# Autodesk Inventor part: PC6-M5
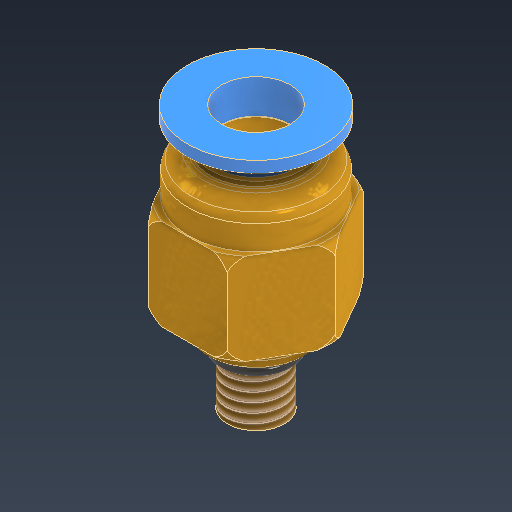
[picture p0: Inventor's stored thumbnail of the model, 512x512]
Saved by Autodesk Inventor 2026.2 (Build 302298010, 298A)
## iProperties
Created: 2026-04
Part Number: PC6-M5
Material: 황동, 연질 노란색, 용접
Document SubType Name: Modeling
Designer: khw
Density: 8.5 g/cm^3
Appearance: 용접 - 황동
Author: khw
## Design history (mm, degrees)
sketch "스케치1"
  geometry: C1 r 2.5 at (0, 0); 1 further point
  constraints: 1 centre point, 1 coincident
  dimensions: "d0" = 5 diameter of C1
extrude "돌출1" new body sketch "스케치1" distance "d1" = 5; taper "d2" = 0 deg
sketch "스케치2"
  geometry: L1 (0, 0)-(8, 0); L2 (8, 0)-(8, -4.5); L3 (5, -2.5)-(5, 2.5) reference; L4 (5, -2.5)-(6.155, -4.5); L5 (6.155, -4.5)-(8, -4.5); 2 further points
  constraints: 8 end point, 2 perpendicular, 1 horizontal, 1 midpoint
  dimensions: "d3" = 3 distance between parallel lines of L2 L3; "d5" = 150 deg angle of L3 L4; "d19" = 9 diameter of point (7.077, -4.5) L1
revolve "회전1" sketch "스케치2" stored, may be unused: angle "d6" = 90 deg
sketch "스케치3"
  geometry: L1 (-6.928, 0)-(-3.464, 6); L2 (-3.464, 6)-(3.464, 6); L3 (3.464, 6)-(6.928, 0); L4 (6.928, 0)-(3.464, -6); L5 (3.464, -6)-(-3.464, -6); L6 (-3.464, -6)-(-6.928, 0); L7 (0, 0)-(-6.928, 0); 1 further point
  constraints: 14 end point, 1 coincident, 1 horizontal, 13 other
  dimensions: "d7" = 12 distance between parallel lines of L3 L6
extrude "돌출2" join sketch "스케치3" distance "d8" = 8; taper "d9" = 0 deg
node "작업 평면1"
sketch "스케치7"
  geometry: L1 (-3.464, 8)-(3.464, 8) reference; L2 (3.464, 8)-(3.464, 16) reference; L3 (-3.464, 16)-(3.464, 16) reference; L4 (-3.464, 8)-(-3.464, 16) reference; L5 (-3.464, 16)-(3.464, 16) reference; L6 (0, 16)-(0, 20); L7 (0, 20)-(4, 20); L8 (4, 20)-(4, 19.6); L9 (4, 19.6)-(4.4, 19.6); L10 (3.464, 16)-(6.928, 16) reference; L11 (5.928, 18.5)-(5.928, 16); L12 (3, 20)-(3, 23); L13 (3, 23)-(0, 23); L14 (3.6, 20)-(3.6, 22); L15 (3.6, 22)-(6, 22); L16 (6, 22)-(6, 23); L17 (6, 23)-(3, 23); L18 (0, 20)-(0, 23); A1 r 3 centre (3.5, 16.738) between (5.928, 18.5) and (4.4, 19.6); 3 further points
  constraints: 24 end point, 8 perpendicular, 4 vertical, 3 point on line, 2 midpoint, 2 point on circle, 1 centre point
  dimensions: "d27" = 0.4 distance of L7.end L8.end; "d28" = 4 distance of L6.end L7.end; "d29" = 0.4 distance of L8.end L9.end; "d30" = 3 radius of A1; "d31" = 4 distance from line of L3 point (2, 20); "d32" = 1 distance from line of L10.end L11; "d33" = 2.5 distance of L11.end L11.start; "d34" = 6 diameter of L12 L6; "d35" = 3 distance between parallel lines of L7 L13; "d36" = 1 distance between parallel lines of L17 L15; "d37" = 0.4 distance from line of L7.end L14; "d38" = 12 diameter of L16 L6
revolve "회전4" sketch "스케치7" stored, may be unused: angle "d39" = 90 deg
sketch "스케치8"
  geometry: C1 r 2.936 at (0, 0); 1 further point
  constraints: 1 centre point, 1 coincident
extrude "돌출3" cut sketch "스케치8" stored distance "d40" = 8; taper "d41" = 0 deg
sketch "스케치9"
  geometry: C1 r 1.5 at (0, 0); 1 further point
  constraints: 1 centre point, 1 coincident
  dimensions: "d42" = 3 diameter of C1
extrude "돌출4" cut sketch "스케치9" distance "d43" = 10; taper "d44" = 0 deg
feature "스레드1" dims "d45" = 5, "d46" = 0
sketch "스케치10"
  geometry: L1 (5, -2.5)-(5, 2.5) reference; L2 (0, 0)-(5, 0); C1 r 0.375 at (4.8, -2.8)
  constraints: 2 end point, 1 centre point, 1 midpoint
  dimensions: "d47" = 0.75 diameter of C1; "d48" = 0.2 distance from line of L1 C1.centre; "d49" = 0.3 vertical distance of L1.start C1.centre
revolve "회전5" sketch "스케치10" stored, may be unused: angle "d50" = 90 deg
sketch "스케치11"
  geometry: L1 (6.928, 16)-(3.464, 16) reference; L2 (6.928, 8)-(3.464, 8) reference; L3 (3.464, 8)-(3.464, 16) reference; L4 (6.928, 16)-(3.464, 16) reference; L5 (6.928, 8)-(6.928, 16) reference; L6 (6.928, 12)-(3.464, 12); L7 (6, 23)-(-6, 23) reference; L8 (0, 23)-(0, 0); A1 r 3 centre (4.042, 14.182) between (6.928, 15) and (6.428, 16); A2 r 3 centre (4.042, 9.818) between (6.428, 8) and (6.928, 9); 3 further points
  constraints: 4 end point, 4 point on circle, 3 midpoint, 3 symmetric about line, 2 centre point, 2 point on line, 1 perpendicular, 1 vertical, 1 other
  dimensions: "d51" = 1 distance of A1.start L1.start; "d52" = 0.5 distance of L1.start A1.end; "d53" = 3 radius of A1
revolve "회전6" sketch "스케치11" stored, may be unused: angle "d54" = 90 deg
fillet "모깎기1" dims "d55" = 1
node "솔리드1"
node "투영된 루프2"
node "투영된 루프3"
feature "A9D066F2-1C7D-4E18-AEED-F7BC21143FA4" dims "d45" = 5, "d46" = 0
